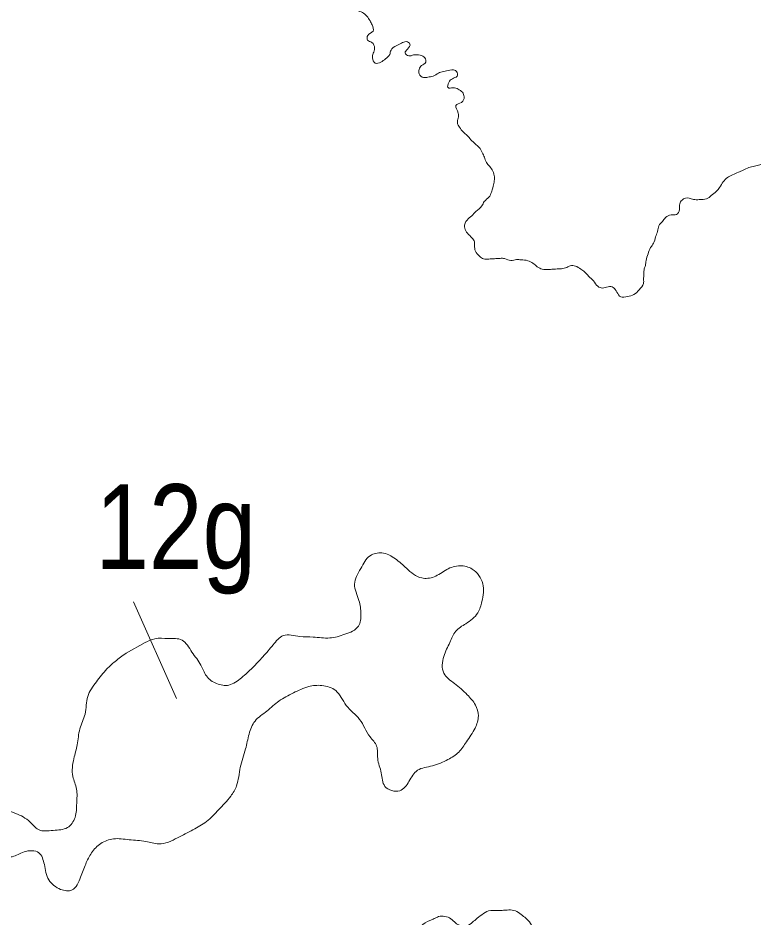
# Model space of a CAD drawing. Extents: x 854879 to 917879, y 8541948 to 8631048.
# Drawn here: x 881265 to 884568, y 8600736 to 8604775 of the extents above; entities that cross this region are included whole.
import ezdxf
from ezdxf.enums import TextEntityAlignment as Align

# ---------------------------------------------------------------- set-up
doc = ezdxf.new("R2010")
doc.units = 0
doc.header["$LTSCALE"] = 150
for name, color, linetype, lineweight in [('1', 7, 'Continuous', 13), ('3', 7, 'Continuous', 13), ('30', 7, 'Continuous', 13), ('52', 7, 'Continuous', 13)]:
    doc.layers.add(name, color=color, linetype=linetype, lineweight=lineweight)

msp = doc.modelspace()

# ---------------------------------------------------------------- linework, layer by layer
at = {"layer": '1'}
msp.add_line((881783.3, 8602155.3), (881976.3, 8601721.3), dxfattribs=at)
at = {"layer": '3'}
for points in [[(882134.4, 8605286.1), (882159.5, 8605277.4), (882179.3, 8605261.3), (882196.2, 8605237.7), (882216.3, 8605231.8), (882241.8, 8605230.7), (882262.7, 8605242.6), (882250.9, 8605266), (882252.1, 8605294), (882272.8, 8605303.3), (882291.1, 8605312.7), (882292, 8605335.6), (882308.1, 8605355.3), (882328.3, 8605349.4), (882348.2, 8605335.9), (882347.3, 8605315.5), (882375, 8605306.7), (882398.2, 8605310.9), (882423.6, 8605309.8), (882420.2, 8605289.6), (882419.3, 8605266.7), (882431.2, 8605245.8), (882456.7, 8605244.7), (882479.4, 8605238.7), (882493.6, 8605212.6), (882492.7, 8605189.8), (882496.9, 8605169.2), (882511.3, 8605145.7), (882510.3, 8605122.8), (882504.3, 8605100.1), (882500.8, 8605077.3), (882499.8, 8605051.9), (882514.2, 8605030.9), (882533.7, 8605007.2), (882555.7, 8604985.9), (882575.8, 8604977.4), (882608.2, 8604958.2), (882628.6, 8604957.4), (882653.5, 8604943.6), (882676, 8604932.5), (882688, 8604914.1), (882697.2, 8604890.8), (882709.2, 8604872.5), (882726.6, 8604859), (882746.5, 8604848), (882766.2, 8604829.4), (882788.3, 8604810.6), (882810.8, 8604799.5), (882830.6, 8604783.4), (882845, 8604762.4), (882854.5, 8604744.2), (882858.5, 8604716), (882834.7, 8604696.6), (882833.9, 8604676.2), (882853.8, 8604665.2), (882865.5, 8604639.3), (882859.5, 8604616.6), (882856.1, 8604596.3), (882867.9, 8604572.9), (882893.6, 8604577), (882914.6, 8604591.4), (882933.2, 8604611), (882939.2, 8604631.1), (882962.9, 8604650.5), (882986.3, 8604662.3), (883007, 8604669.1), (883024.4, 8604658.2), (883013.3, 8604635.7), (883002.4, 8604618.3), (883019.7, 8604604.9), (883040.3, 8604609.1), (883070.8, 8604607.8), (883090.8, 8604596.8), (883095.1, 8604576.3), (883076.6, 8604561.8), (883065.7, 8604544.4), (883064.9, 8604524), (883084.6, 8604507.9), (883105.1, 8604509.6), (883128.2, 8604513.8), (883151.8, 8604528.1), (883175, 8604534.8), (883203.3, 8604541.2), (883233.7, 8604534.9), (883235.4, 8604514.4), (883214.5, 8604502.5), (883198.5, 8604485.4), (883195, 8604462.6), (883217.9, 8604461.6), (883240.6, 8604455.6), (883260.5, 8604442)], [(882134.4, 8605286.1), (882159.5, 8605277.4), (882179.3, 8605261.3), (882196.2, 8605237.7), (882216.3, 8605231.8), (882241.8, 8605230.7), (882262.7, 8605242.6), (882250.9, 8605266), (882252.1, 8605294), (882272.8, 8605303.3), (882291.1, 8605312.7), (882292, 8605335.6), (882308.1, 8605355.3), (882328.3, 8605349.4), (882348.2, 8605335.9), (882347.3, 8605315.5), (882375, 8605306.7), (882398.2, 8605310.9), (882423.6, 8605309.8), (882420.2, 8605289.6), (882419.3, 8605266.7), (882431.2, 8605245.8), (882456.7, 8605244.7), (882479.4, 8605238.7), (882493.6, 8605212.6), (882492.7, 8605189.8), (882496.9, 8605169.2), (882511.3, 8605145.7), (882510.3, 8605122.8), (882504.3, 8605100.1), (882500.8, 8605077.3), (882499.8, 8605051.9), (882514.2, 8605030.9), (882533.7, 8605007.2), (882555.7, 8604985.9), (882575.8, 8604977.4), (882608.2, 8604958.2), (882628.6, 8604957.4), (882653.5, 8604943.6), (882676, 8604932.5), (882688, 8604914.1), (882697.2, 8604890.8), (882709.2, 8604872.5), (882726.6, 8604859), (882746.5, 8604848), (882766.2, 8604829.4), (882788.3, 8604810.6), (882810.8, 8604799.5), (882830.6, 8604783.4), (882845, 8604762.4), (882854.5, 8604744.2), (882858.5, 8604716), (882834.7, 8604696.6), (882833.9, 8604676.2), (882853.8, 8604665.2), (882865.5, 8604639.3), (882859.5, 8604616.6), (882856.1, 8604596.3), (882867.9, 8604572.9), (882893.6, 8604577), (882914.6, 8604591.4), (882933.2, 8604611), (882939.2, 8604631.1), (882962.9, 8604650.5), (882986.3, 8604662.3), (883007, 8604669.1), (883024.4, 8604658.2), (883013.3, 8604635.7), (883002.4, 8604618.3), (883019.7, 8604604.9), (883040.3, 8604609.1), (883070.8, 8604607.8), (883090.8, 8604596.8), (883095.1, 8604576.3), (883076.6, 8604561.8), (883065.7, 8604544.4), (883064.9, 8604524), (883084.6, 8604507.9), (883105.1, 8604509.6), (883128.2, 8604513.8), (883151.8, 8604528.1), (883175, 8604534.8), (883203.3, 8604541.2), (883233.7, 8604534.9), (883235.4, 8604514.4), (883214.5, 8604502.5), (883198.5, 8604485.4), (883195, 8604462.6), (883217.9, 8604461.6), (883240.6, 8604455.6), (883260.5, 8604442)], [(884400.4, 8603997.4), (884413.8, 8604014.7), (884430.2, 8604039.5), (884448.8, 8604059.1), (884472.3, 8604070.9), (884498.2, 8604082.6), (884519, 8604091.9), (884545, 8604103.6), (884570.8, 8604110.1), (884594, 8604116.8), (884622.5, 8604125.8), (884650.8, 8604132.3), (884679.1, 8604138.8), (884712.6, 8604147.6), (884751.3, 8604156.2), (884771.8, 8604160.4), (884792.4, 8604164.7), (884813.6, 8604184.2), (884834.9, 8604206.2), (884856.2, 8604228.3), (884882.5, 8604245), (884921.2, 8604256.2), (884944.7, 8604270.5), (884963.1, 8604282.5), (884981.6, 8604299.5), (885007.7, 8604313.7), (885028.7, 8604328.2), (885039.8, 8604350.6), (885056.2, 8604375.4), (885072.3, 8604395.1), (885090.8, 8604412.2), (885116.7, 8604421.3), (885137.4, 8604428.1), (885158.1, 8604434.9), (885183.9, 8604441.5), (885202.2, 8604453.5), (885225.8, 8604467.8), (885241.9, 8604487.5), (885247.8, 8604507.6), (885256.6, 8604535.3), (885279.3, 8604529.3), (885304, 8604510.4), (885308.1, 8604484.8), (885306.9, 8604456.8), (885306, 8604433.9), (885302.6, 8604413.7), (885299.2, 8604393.4), (885305.8, 8604367.7), (885320, 8604339), (885334.6, 8604323.2), (885343.8, 8604297.3), (885353.2, 8604279.1), (885362.2, 8604250.7), (885366.2, 8604222.5), (885383, 8604196.3), (885402.8, 8604182.7), (885422.9, 8604174.3), (885443.3, 8604173.4), (885468.7, 8604172.4), (885489.7, 8604186.8), (885505.8, 8604206.5), (885512.2, 8604236.8), (885537.9, 8604240.8), (885562.9, 8604229.6), (885585.3, 8604216), (885610.4, 8604204.7), (885632.9, 8604193.6), (885650.3, 8604182.7), (885672.4, 8604161.4), (885689.8, 8604150.5), (885709.6, 8604136.9), (885729.8, 8604131), (885759.7, 8604114.5), (885779.9, 8604108.5), (885805, 8604099.9), (885835.4, 8604093.5), (885858, 8604084.9), (885878.7, 8604091.7), (885909, 8604085.4), (885931.3, 8604069.2), (885940.7, 8604048.4), (885962.9, 8604029.6), (885983.2, 8604028.8), (886019.1, 8604032.4), (886042.7, 8604046.7), (886065.9, 8604053.4), (886091, 8604044.7), (886111, 8604033.7), (886131.1, 8604025.2), (886148.2, 8604009.2), (886180.3, 8603996.9)], [(884400.4, 8603997.4), (884413.8, 8604014.7), (884430.2, 8604039.5), (884448.8, 8604059.1), (884472.3, 8604070.9), (884498.2, 8604082.6), (884519, 8604091.9), (884545, 8604103.6), (884570.8, 8604110.1), (884594, 8604116.8), (884622.5, 8604125.8), (884650.8, 8604132.3), (884679.1, 8604138.8), (884712.6, 8604147.6), (884751.3, 8604156.2), (884771.8, 8604160.4), (884792.4, 8604164.7), (884813.6, 8604184.2), (884834.9, 8604206.2), (884856.2, 8604228.3), (884882.5, 8604245), (884921.2, 8604256.2), (884944.7, 8604270.5), (884963.1, 8604282.5), (884981.6, 8604299.5), (885007.7, 8604313.7), (885028.7, 8604328.2), (885039.8, 8604350.6), (885056.2, 8604375.4), (885072.3, 8604395.1), (885090.8, 8604412.2), (885116.7, 8604421.3), (885137.4, 8604428.1), (885158.1, 8604434.9), (885183.9, 8604441.5), (885202.2, 8604453.5), (885225.8, 8604467.8), (885241.9, 8604487.5), (885247.8, 8604507.6), (885256.6, 8604535.3), (885279.3, 8604529.3), (885304, 8604510.4), (885308.1, 8604484.8), (885306.9, 8604456.8), (885306, 8604433.9), (885302.6, 8604413.7), (885299.2, 8604393.4), (885305.8, 8604367.7), (885320, 8604339), (885334.6, 8604323.2), (885343.8, 8604297.3), (885353.2, 8604279.1), (885362.2, 8604250.7), (885366.2, 8604222.5), (885383, 8604196.3), (885402.8, 8604182.7), (885422.9, 8604174.3), (885443.3, 8604173.4), (885468.7, 8604172.4), (885489.7, 8604186.8), (885505.8, 8604206.5), (885512.2, 8604236.8), (885537.9, 8604240.8), (885562.9, 8604229.6), (885585.3, 8604216), (885610.4, 8604204.7), (885632.9, 8604193.6), (885650.3, 8604182.7), (885672.4, 8604161.4), (885689.8, 8604150.5), (885709.6, 8604136.9), (885729.8, 8604131), (885759.7, 8604114.5), (885779.9, 8604108.5), (885805, 8604099.9), (885835.4, 8604093.5), (885858, 8604084.9), (885878.7, 8604091.7), (885909, 8604085.4), (885931.3, 8604069.2), (885940.7, 8604048.4), (885962.9, 8604029.6), (885983.2, 8604028.8), (886019.1, 8604032.4), (886042.7, 8604046.7), (886065.9, 8604053.4), (886091, 8604044.7), (886111, 8604033.7), (886131.1, 8604025.2), (886148.2, 8604009.2), (886180.3, 8603996.9)], [(883260.5, 8604442), (883267.3, 8604421.4), (883256.1, 8604396.4), (883230, 8604382.2), (883241.3, 8604348.6), (883240.4, 8604325.7), (883237, 8604305.4), (883246.4, 8604284.7), (883263.4, 8604263.6), (883280.6, 8604247.6), (883297.7, 8604229), (883317.3, 8604210.4), (883334.5, 8604194.4), (883348.8, 8604170.9), (883358.2, 8604150.1), (883367.4, 8604126.8), (883382, 8604108.3), (883396.4, 8604087.4), (883403, 8604061.6), (883402.1, 8604038.7), (883396, 8604013.5), (883390, 8603993.3), (883378.9, 8603970.9), (883357.7, 8603951.4), (883346.7, 8603931.4), (883320.2, 8603907.1), (883301.5, 8603887.4), (883280.3, 8603867.9), (883268.9, 8603837.8), (883278.1, 8603814.5), (883297.7, 8603793.3), (883312.2, 8603774.9), (883313.9, 8603754.4), (883318, 8603728.8), (883337.4, 8603705.1), (883354.8, 8603694.2), (883377.7, 8603693.2), (883403.3, 8603694.7), (883428.9, 8603696.2), (883449.2, 8603695.3), (883477, 8603686.6), (883502.6, 8603690.6), (883523, 8603689.8), (883553.5, 8603685.9), (883576, 8603674.8), (883595.7, 8603658.7), (883618.2, 8603647.6), (883648.8, 8603646.3), (883671.8, 8603647.9), (883697.4, 8603649.4), (883723, 8603653.4), (883743.8, 8603662.8), (883766.7, 8603661.8), (883791.7, 8603648.1), (883809, 8603634.6), (883826.1, 8603616.1), (883848.2, 8603594.8), (883867.6, 8603571), (883887.7, 8603562.6), (883913.5, 8603569.1), (883936.3, 8603565.7), (883953.3, 8603544.6), (883970.2, 8603523.5), (884000.9, 8603524.8), (884029.3, 8603533.8), (884053.2, 8603555.7), (884072.2, 8603583), (884073, 8603603.3), (884073.8, 8603623.7), (884074.7, 8603644), (884080.6, 8603664.1), (884084.1, 8603686.9), (884093, 8603717.1), (884104.3, 8603744.7), (884117.9, 8603764.5), (884126.7, 8603792.2), (884135.3, 8603817.3), (884141.5, 8603842.5), (884157.6, 8603862.2), (884171.1, 8603879.5), (884197.1, 8603891.2), (884220.1, 8603892.8), (884233.7, 8603915.1), (884234.8, 8603940.6), (884245.7, 8603958), (884276.7, 8603966.9), (884296.8, 8603960.9), (884322.3, 8603959.9), (884355.6, 8603963.6), (884376.6, 8603978), (884400.4, 8603997.4)], [(883260.5, 8604442), (883267.3, 8604421.4), (883256.1, 8604396.4), (883230, 8604382.2), (883241.3, 8604348.6), (883240.4, 8604325.7), (883237, 8604305.4), (883246.4, 8604284.7), (883263.4, 8604263.6), (883280.6, 8604247.6), (883297.7, 8604229), (883317.3, 8604210.4), (883334.5, 8604194.4), (883348.8, 8604170.9), (883358.2, 8604150.1), (883367.4, 8604126.8), (883382, 8604108.3), (883396.4, 8604087.4), (883403, 8604061.6), (883402.1, 8604038.7), (883396, 8604013.5), (883390, 8603993.3), (883378.9, 8603970.9), (883357.7, 8603951.4), (883346.7, 8603931.4), (883320.2, 8603907.1), (883301.5, 8603887.4), (883280.3, 8603867.9), (883268.9, 8603837.8), (883278.1, 8603814.5), (883297.7, 8603793.3), (883312.2, 8603774.9), (883313.9, 8603754.4), (883318, 8603728.8), (883337.4, 8603705.1), (883354.8, 8603694.2), (883377.7, 8603693.2), (883403.3, 8603694.7), (883428.9, 8603696.2), (883449.2, 8603695.3), (883477, 8603686.6), (883502.6, 8603690.6), (883523, 8603689.8), (883553.5, 8603685.9), (883576, 8603674.8), (883595.7, 8603658.7), (883618.2, 8603647.6), (883648.8, 8603646.3), (883671.8, 8603647.9), (883697.4, 8603649.4), (883723, 8603653.4), (883743.8, 8603662.8), (883766.7, 8603661.8), (883791.7, 8603648.1), (883809, 8603634.6), (883826.1, 8603616.1), (883848.2, 8603594.8), (883867.6, 8603571), (883887.7, 8603562.6), (883913.5, 8603569.1), (883936.3, 8603565.7), (883953.3, 8603544.6), (883970.2, 8603523.5), (884000.9, 8603524.8), (884029.3, 8603533.8), (884053.2, 8603555.7), (884072.2, 8603583), (884073, 8603603.3), (884073.8, 8603623.7), (884074.7, 8603644), (884080.6, 8603664.1), (884084.1, 8603686.9), (884093, 8603717.1), (884104.3, 8603744.7), (884117.9, 8603764.5), (884126.7, 8603792.2), (884135.3, 8603817.3), (884141.5, 8603842.5), (884157.6, 8603862.2), (884171.1, 8603879.5), (884197.1, 8603891.2), (884220.1, 8603892.8), (884233.7, 8603915.1), (884234.8, 8603940.6), (884245.7, 8603958), (884276.7, 8603966.9), (884296.8, 8603960.9), (884322.3, 8603959.9), (884355.6, 8603963.6), (884376.6, 8603978), (884400.4, 8603997.4)]]:
    msp.add_spline(points, degree=3, dxfattribs=at)
at = {"layer": '30'}
msp.add_line((881750.1, 8601924.4), (881835.4, 8601971.8), dxfattribs=at)
for points in [[(881835.4, 8601971.8), (881879.7, 8601989.4), (881938.8, 8601990.3), (882001.5, 8601983.1), (882045.9, 8601929), (882086.2, 8601871.1), (882111.1, 8601822.1), (882156.6, 8601787.8), (882211.4, 8601781), (882268.3, 8601813.9), (882318.1, 8601859.1), (882364.1, 8601908.5), (882410.3, 8601961.9), (882455.9, 8602003.3), (882530.6, 8601999.4), (882589.5, 8601996.4), (882664.2, 8601992.5), (882732.1, 8602008.9), (882793.2, 8602045.5), (882804, 8602100.7), (882795.4, 8602160.9), (882775.7, 8602233.7), (882803.1, 8602303.9), (882845.7, 8602361.5), (882897.6, 8602374.7), (882959.2, 8602347.6), (883008.2, 8602305.2), (883076.8, 8602261.8), (883132.2, 8602266.9), (883189.2, 8602299.8), (883249.2, 8602316.6), (883303.6, 8602301.8), (883351.3, 8602235.6), (883347, 8602156.2), (883328.5, 8602105.4), (883274.6, 8602056.4), (883229.5, 8602022.9), (883203.1, 8601972.5), (883176.1, 8601910.1), (883176, 8601834.5), (883224.7, 8601788.1), (883281.1, 8601737.4), (883318, 8601691.7), (883331.2, 8601643.2), (883316.4, 8601588.2), (883277.6, 8601526.5), (883243.6, 8601480.4), (883194.5, 8601447.1), (883126, 8601418.8), (883057.9, 8601398.5), (883019.7, 8601348.7), (882978.1, 8601307), (882912.1, 8601326.4), (882895.7, 8601387), (882879.4, 8601451.6), (882874.6, 8601507.6), (882845.3, 8601548.9), (882798.2, 8601627), (882738.6, 8601689.9), (882690.9, 8601756.1), (882629.1, 8601779.2), (882569.7, 8601774.3), (882501.2, 8601746), (882436.1, 8601709.6), (882382.5, 8601664.6), (882328.8, 8601619.6), (882302, 8601561.2), (882286.6, 8601494.3), (882262.4, 8601411.9), (882246.2, 8601329.1), (882220, 8601282.7), (882165.5, 8601221.8), (882111.4, 8601168.8), (882050.3, 8601132.1), (881981.4, 8601095.9), (881897.1, 8601068.4), (881838.6, 8601079.4), (881764.1, 8601087.2), (881693.4, 8601090.9), (881637.1, 8601069.9), (881595.4, 8601028.3), (881569, 8600977.9), (881546.2, 8600919.3), (881507.6, 8600861.6), (881456.5, 8600864.2), (881403.6, 8600906.8), (881383.7, 8600975.6)], [(881383.7, 8600975.6), (881358.9, 8601028.6), (881292.1, 8601032.1), (881239.7, 8601010.9), (881180.8, 8601014), (881118.3, 8601025.2), (881063.7, 8601036), (880988.2, 8601024), (880938.7, 8600982.7), (880896.6, 8600933.1), (880832.3, 8600836.9), (880806.1, 8600790.5), (880776.3, 8600748.2), (880729.2, 8600678.9), (880698.7, 8600624.8), (880651.6, 8600555.5), (880609.1, 8600498), (880541.9, 8600421.8), (880491.8, 8600368.6), (880441, 8600303.6), (880404.8, 8600217.8), (880405.3, 8600154.1), (880413.3, 8600081.9), (880410.3, 8600026.3), (880402.9, 8599963), (880370.7, 8599877), (880340, 8599818.9), (880288.6, 8599741.9), (880236.6, 8599728.6), (880178.7, 8599751.6), (880149.8, 8599800.9), (880130.1, 8599873.6), (880134, 8599945.1), (880153.1, 8600007.8), (880164.8, 8600078.9), (880168.4, 8600146.4), (880139.3, 8600191.8), (880087.5, 8600254.2), (880058.2, 8600295.6), (880041.3, 8600348.2), (880044.6, 8600407.8), (880067.4, 8600466.3), (880097.5, 8600512.6), (880143.5, 8600562), (880200.2, 8600590.9), (880268.3, 8600611.3), (880327.7, 8600616.1), (880399.1, 8600624.4), (880441, 8600670), (880478.3, 8600703.9), (880493.9, 8600774.8), (880509.3, 8600841.7), (880524.1, 8600896.7), (880527.3, 8600956.3), (880531.4, 8601031.8), (880544.4, 8601126.7), (880556.3, 8601201.7), (880568.2, 8601276.8), (880575.6, 8601340.2), (880591.9, 8601423), (880603.2, 8601486.1), (880643.2, 8601571.7), (880688.8, 8601613.1), (880755.6, 8601609.6), (880812.2, 8601562.9), (880845.5, 8601521.3), (880882.4, 8601475.6), (880934, 8601409.2), (880969.5, 8601335.6), (881010.8, 8601297.6), (881048.2, 8601259.8), (881113.3, 8601224.6), (881176.2, 8601221.3), (881254.2, 8601205.3), (881319, 8601166.1), (881356.6, 8601132.3), (881423.5, 8601128.8), (881487.2, 8601141.5), (881521.2, 8601187.5), (881528.6, 8601250.8), (881528, 8601314.6), (881511.4, 8601371.2), (881515.7, 8601450.7), (881530.9, 8601513.6), (881542.6, 8601584.7), (881565.9, 8601651.2), (881578, 8601730.2), (881617, 8601795.9), (881663.5, 8601853.3), (881700.8, 8601887.2), (881750.1, 8601924.4)]]:
    msp.add_spline(points, degree=3, dxfattribs=at)
at = {"layer": '52'}
msp.add_spline([(883654.2, 8600469.3), (883648.9, 8600504.9), (883636.1, 8600528.2), (883623.2, 8600555.4), (883610.4, 8600578.8), (883609.3, 8600606.5), (883599.9, 8600645.9), (883586.7, 8600681.1), (883569.9, 8600704.2), (883549.1, 8600731.2), (883528.7, 8600746.2), (883504.2, 8600765), (883476.2, 8600771.8), (883444.6, 8600770.4), (883416.9, 8600769.2), (883377.3, 8600767.5), (883346.3, 8600750.3), (883319.4, 8600729.3), (883300.2, 8600712.6), (883273, 8600699.5), (883249.1, 8600702.4), (883228.9, 8600713.5), (883208.4, 8600732.5), (883180.2, 8600743.2), (883152.6, 8600742), (883133.1, 8600733.2), (883113.6, 8600724.5), (883075, 8600699), (883060.5, 8600662.6), (883049.9, 8600630.3), (883051.4, 8600590.6), (883052.3, 8600566.8), (883057.1, 8600547.2), (883066.3, 8600511.8), (883079, 8600492.4), (883100, 8600461.5), (883120.1, 8600454.4), (883148.5, 8600435.8), (883180.9, 8600417.3), (883200.8, 8600414.2), (883228.5, 8600415.4), (883256.6, 8600404.6), (883288.9, 8600390.1), (883313.7, 8600363.3), (883326.5, 8600340.1), (883335.6, 8600308.6), (883348.5, 8600281.4), (883350.1, 8600241.7), (883355.1, 8600214.1), (883367.9, 8600190.8), (883388.6, 8600167.8), (883416.8, 8600153.1), (883437.4, 8600134.1), (883457.3, 8600131), (883489.3, 8600124.4), (883521.4, 8600113.9), (883541.6, 8600102.8), (883573.8, 8600088.3), (883594.4, 8600069.3), (883619, 8600046.5), (883643.8, 8600019.7), (883656.8, 8599992.4), (883669.8, 8599961.2), (883682.9, 8599930), (883695.8, 8599902.7), (883704.8, 8599875.3), (883706.8, 8599823.7), (883703.6, 8599803.7), (883700.9, 8599771.7), (883689.8, 8599751.4), (883678.7, 8599731.1), (883663.6, 8599710.5), (883664.7, 8599682.8), (883657.7, 8599658.6), (883658.9, 8599626.9), (883659.9, 8599603), (883661.1, 8599571.3), (883677.8, 8599548.2), (883694.7, 8599521.1), (883739.4, 8599491.2), (883759.8, 8599476.2), (883788.4, 8599453.5), (883824.5, 8599443.1), (883852.8, 8599428.4), (883876.8, 8599421.5), (883897.2, 8599406.5), (883946.2, 8599368.8), (883971, 8599342.1), (883987.5, 8599322.9), (884008.5, 8599292), (884111.1, 8599097.7)], degree=3, dxfattribs=at)

# ---------------------------------------------------------------- texts
at = {"layer": '1', "width": 0.85}
msp.add_text('12g', height=380, dxfattribs=at).set_placement((881973, 8602302.7), align=Align.CENTER)

doc.saveas('drawing.dxf')
